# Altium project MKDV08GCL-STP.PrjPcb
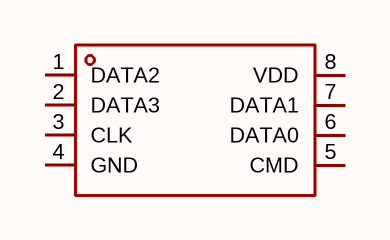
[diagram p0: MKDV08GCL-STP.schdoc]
1 sheet, 1 parts. Net scope: global (net labels, ports and power ports of the same name join across sheets).

## Sheet MKDV08GCL-STP.schdoc
size 127 x 101 mm

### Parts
U?  mkdv08gcl-stp  [LGA-8_L8.0-W6.6-P1.27-TL_MKDV16GCL-STP]  (value not drawn)

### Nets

Not connected (* = marked no-connect by the designer): U? 1(DATA2) 2(DATA3) 3(CLK) 4(GND) 5(CMD) 6(DATA0) 7(DATA1) 8(VDD)

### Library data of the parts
U? = mkdv08gcl-stp: 存储容量:8Gbit;时钟频率(fc):50MHz;工作电压:2.7V~3.6V;; Manufacturer: MK(米客方德); AddInBom: yes; ModelId: cb666697461d4e7fa3ab5c9a2ecf3791; ModelTransform: 314.96,259.842,0,0,0,0,0,0,0; Memory Size: 8Gbit; Interface: SD接口；SPI; Clock Frequency: 50MHz; Standby Supply Current: 250uA; Program / Erase Cycles: 5千次; ECC: 有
